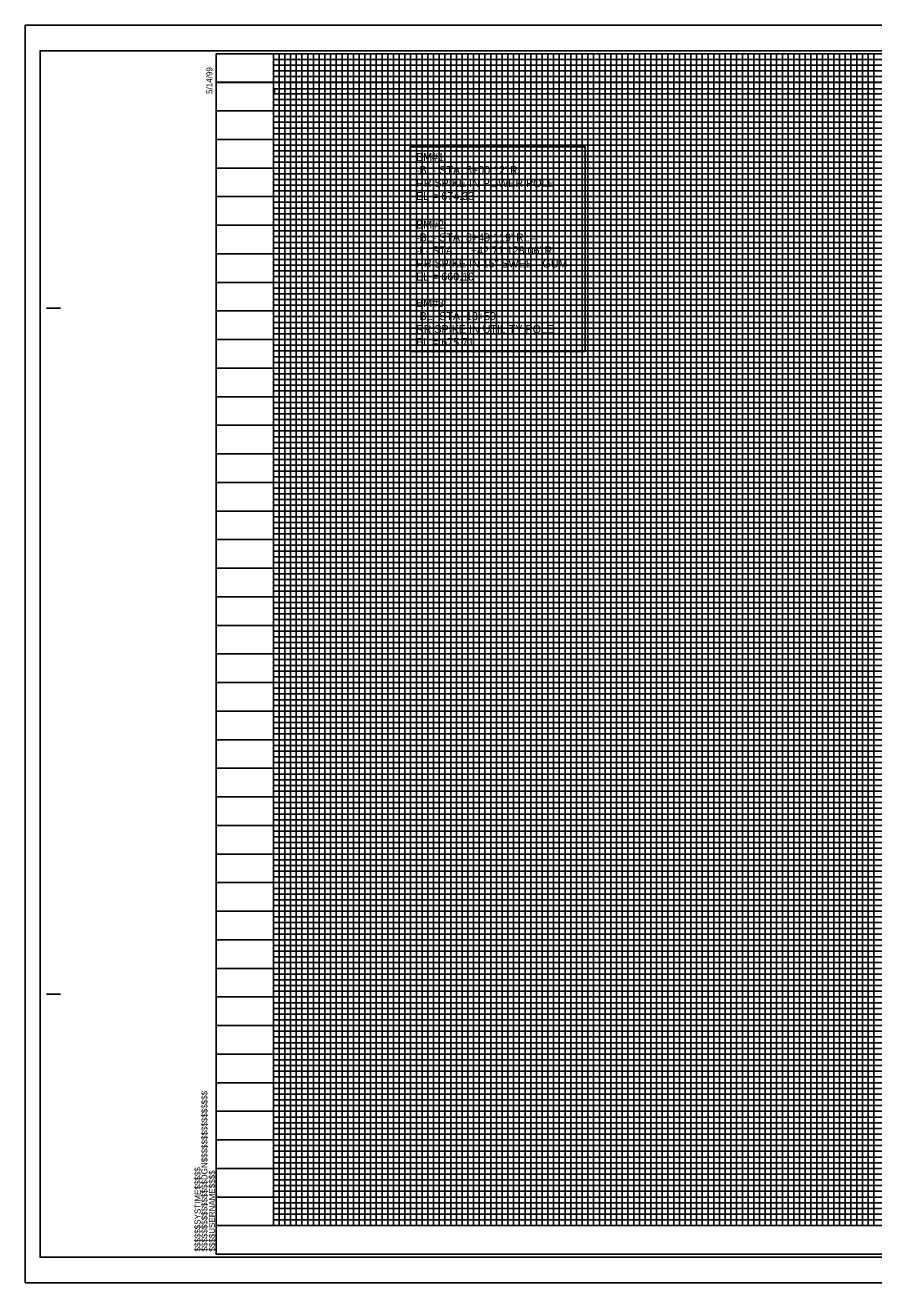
# Model space of a CAD drawing. Extents: x 566462 to 568359, y -52789 to -51689.
import ezdxf

# ---------------------------------------------------------------- set-up
doc = ezdxf.new("R2010")
doc.units = 0
for name, color, linetype in [('Prop Grid Mask', 7, 'Continuous'), ('Prop Roadway Profile Bench Mark Info Text', 7, 'Continuous'), ('Sheet Cutting Line CELL', 7, 'Continuous'), ('Sheet DOT Grid CELL', 7, 'Continuous'), ('Sheet Layout Profile Border', 7, 'Continuous'), ('Sheet Plot Border Inside CELL', 7, 'Continuous'), ('Sheet Plot Border Outside CELL', 7, 'Continuous'), ('Sheet Profile CELL', 7, 'Continuous'), ('Sheet Profile Grid Major CELL', 7, 'Continuous'), ('Sheet Profile Grid Middle CELL', 7, 'Continuous'), ('Sheet Profile Grid Minor CELL', 7, 'Continuous')]:
    doc.layers.add(name, color=color, linetype=linetype)

msp = doc.modelspace()

# ---------------------------------------------------------------- linework, layer by layer
at = {"layer": 'Prop Grid Mask'}
msp.add_lwpolyline([(566799.2, -51795.9), (566952, -51795.9), (566952, -51974.8), (566799.2, -51974.8)], close=True, dxfattribs=at)
at = {"layer": 'Sheet Cutting Line CELL'}
for p, q in [((568146.5, -51689.3), (566462.5, -51689.3)), ((566462.5, -51689.3), (566462.5, -52789.3)), ((566462.5, -52789.3), (568146.5, -52789.3))]:
    msp.add_line(p, q, dxfattribs=at)
at = {"layer": 'Sheet DOT Grid CELL'}
for p, q in [((566679.5, -51714.3), (566679.5, -52739.3)), ((566729.5, -51714.3), (566729.5, -52739.3)), ((566779.5, -51714.3), (566779.5, -52739.3)), ((566829.5, -51714.3), (566829.5, -52739.3)), ((566879.5, -51714.3), (566879.5, -52739.3)), ((566929.5, -51714.3), (566929.5, -52739.3)), ((566979.5, -51714.3), (566979.5, -52739.3)), ((567029.5, -51714.3), (567029.5, -52739.3)), ((567079.5, -51714.3), (567079.5, -52739.3)), ((567129.5, -51714.3), (567129.5, -52739.3)), ((567179.5, -51714.3), (567179.5, -52739.3)), ((566629.5, -51739.3), (567929.4, -51739.3)), ((566629.5, -51789.3), (567929.4, -51789.3)), ((566629.5, -51839.3), (567929.4, -51839.3)), ((566629.5, -51889.3), (568129.5, -51889.3)), ((566629.5, -51939.3), (568129.5, -51939.3)), ((566629.5, -51989.3), (568129.5, -51989.3)), ((566629.5, -52039.3), (568129.5, -52039.3)), ((566629.5, -52089.3), (568129.5, -52089.3)), ((566629.5, -52139.3), (568129.5, -52139.3)), ((566629.5, -52189.3), (568129.5, -52189.3)), ((566629.5, -52239.3), (568129.5, -52239.3)), ((566629.5, -52289.3), (568129.5, -52289.3)), ((566629.5, -52339.3), (568129.5, -52339.3)), ((566629.5, -52389.3), (568129.5, -52389.3)), ((566629.5, -52439.3), (568129.5, -52439.3)), ((566629.5, -52489.3), (568129.5, -52489.3)), ((566629.5, -52539.3), (568129.5, -52539.3)), ((566629.5, -52589.3), (568129.5, -52589.3)), ((566629.5, -52639.3), (568129.5, -52639.3)), ((566629.5, -52689.3), (568129.5, -52689.3))]:
    msp.add_line(p, q, dxfattribs=at)
at = {"layer": 'Sheet Layout Profile Border'}
msp.add_lwpolyline([(566679.5, -51714.3), (566679.5, -52739.3), (568079.5, -52739.3), (568079.5, -51851.9), (567929.4, -51851.9), (567929.4, -51714.3)], close=True, dxfattribs=at)
at = {"layer": 'Sheet Plot Border Inside CELL'}
msp.add_lwpolyline([(568142, -51711.8), (566475.5, -51711.8), (566475.5, -52766.9), (568142, -52766.9)], close=True, dxfattribs=at)
at = {"layer": 'Sheet Plot Border Outside CELL'}
msp.add_lwpolyline([(568146.5, -51689.3), (566462.5, -51689.3), (566462.5, -52789.3), (568146.5, -52789.3)], close=True, dxfattribs=at)
at = {"layer": 'Sheet Profile CELL'}
for p, q in [((566481, -51936.8), (566493.5, -51936.8)), ((566481, -52536.8), (566493.5, -52536.8)), ((568129.5, -52739.3), (566629.5, -52739.3)), ((566629.5, -52764.3), (566629.5, -52764.3)), ((566629.5, -52764.3), (566629.5, -52764.3)), ((566629.5, -52764.3), (566629.5, -52764.3)), ((566629.5, -52764.3), (566629.5, -52764.3)), ((566629.5, -52764.3), (566629.5, -52764.3)), ((566629.5, -52764.3), (566629.5, -52764.3))]:
    msp.add_line(p, q, dxfattribs=at)
msp.add_lwpolyline([(568129.5, -51714.3), (566629.5, -51714.3), (566629.5, -52764.3), (568129.5, -52764.3)], close=True, dxfattribs=at)
msp.add_lwpolyline([(566667, -52764.3), (566667, -52764.3)], dxfattribs=at)
at = {"layer": 'Sheet Profile Grid Major CELL'}
for points in [[(566629.5, -51714.3), (566679.5, -51714.3), (566679.5, -52739.3), (566729.5, -52739.3), (566729.5, -51714.3), (566779.5, -51714.3), (566779.5, -52739.3), (566829.5, -52739.3), (566829.5, -51714.3), (566879.5, -51714.3), (566879.5, -52739.3), (566929.5, -52739.3), (566929.5, -51714.3), (566979.5, -51714.3), (566979.5, -52739.3), (567029.5, -52739.3), (567029.5, -51714.3), (567079.5, -51714.3), (567079.5, -52739.3), (567129.5, -52739.3), (567129.5, -51714.3), (567179.5, -51714.3), (567179.5, -52739.3), (567229.5, -52739.3)], [(567929.4, -51789.3), (566629.6, -51789.3), (566629.6, -51739.4), (567929.4, -51739.4)], [(568129.5, -51889.3), (566629.5, -51889.3), (566629.5, -51839.3), (567929.4, -51839.3)], [(568129.5, -51989.3), (566629.5, -51989.3), (566629.5, -51939.3), (568129.5, -51939.3)], [(568129.5, -52089.3), (566629.5, -52089.3), (566629.5, -52039.3), (568129.5, -52039.3)], [(568129.5, -52189.3), (566629.5, -52189.3), (566629.5, -52139.3), (568129.5, -52139.3)], [(568129.5, -52289.3), (566629.5, -52289.3), (566629.5, -52239.3), (568129.5, -52239.3)], [(568129.5, -52389.3), (566629.5, -52389.3), (566629.5, -52339.3), (568129.5, -52339.3)], [(568129.5, -52489.3), (566629.5, -52489.3), (566629.5, -52439.3), (568129.5, -52439.3)], [(568129.5, -52589.3), (566629.5, -52589.3), (566629.5, -52539.3), (568129.5, -52539.3)], [(568129.5, -52689.3), (566629.5, -52689.3), (566629.5, -52639.3), (568129.5, -52639.3)]]:
    msp.add_lwpolyline(points, dxfattribs=at)
at = {"layer": 'Sheet Profile Grid Middle CELL'}
for points in [[(566704.5, -52739.3), (566704.5, -51714.3), (566754.5, -51714.3), (566754.5, -52739.3), (566804.5, -52739.3), (566804.5, -51714.3), (566854.5, -51714.3), (566854.5, -52739.3), (566904.5, -52739.3), (566904.5, -51714.3), (566954.5, -51714.3), (566954.5, -52739.3), (567004.5, -52739.3), (567004.5, -51714.3), (567054.5, -51714.3), (567054.5, -52739.3), (567104.5, -52739.3), (567104.5, -51714.3), (567154.5, -51714.3), (567154.5, -52739.3), (567204.5, -52739.3), (567204.5, -51714.3), (567254.5, -51714.3)], [(566629.5, -51764.3), (567929.4, -51764.3)], [(567929.4, -51814.3), (566629.5, -51814.3), (566629.5, -51864.4), (568129.5, -51864.4)], [(568129.5, -51914.3), (566629.5, -51914.3), (566629.5, -51964.3), (568129.5, -51964.3)], [(568129.5, -52014.3), (566629.5, -52014.3), (566629.5, -52064.3), (568129.5, -52064.3)], [(568129.5, -52114.3), (566629.5, -52114.3), (566629.5, -52164.3), (568129.5, -52164.3)], [(568129.5, -52214.3), (566629.5, -52214.3), (566629.5, -52264.3), (568129.5, -52264.3)], [(568129.5, -52314.3), (566629.5, -52314.3), (566629.5, -52364.3), (568129.5, -52364.3)], [(568129.5, -52414.3), (566629.5, -52414.3), (566629.5, -52464.3), (568129.5, -52464.3)], [(568129.5, -52514.3), (566629.5, -52514.3), (566629.5, -52564.3), (568129.5, -52564.3)], [(568129.5, -52614.3), (566629.5, -52614.3), (566629.5, -52664.3), (568129.5, -52664.3)], [(568129.5, -52714.3), (566629.5, -52714.3)]]:
    msp.add_lwpolyline(points, dxfattribs=at)
at = {"layer": 'Sheet Profile Grid Minor CELL'}
for p, q in [((568079.5, -51894.3), (566679.5, -51894.3)), ((566679.5, -51894.3), (566679.5, -51899.3)), ((566679.5, -51899.3), (568079.5, -51899.3)), ((568079.5, -51919.3), (566679.5, -51919.3))]:
    msp.add_line(p, q, dxfattribs=at)
for points in [[(566684.5, -51714.3), (566689.5, -51714.3), (566694.5, -51714.3), (566699.5, -51714.3), (566709.5, -51714.3), (566676.4, -51714.3), (566681.4, -51714.3), (566639.5, -51714.3), (566644.5, -51714.3), (566649.5, -51714.3), (566659.5, -51714.3), (566664.5, -51714.3), (566669.5, -51714.3), (566674.5, -51714.3), (566684.5, -51714.3), (566684.5, -52739.3), (566689.5, -52739.3), (566689.5, -51714.3), (566694.5, -51714.3), (566694.5, -52739.3), (566699.5, -52739.3), (566699.5, -51714.3), (566709.5, -51714.3), (566709.5, -52739.3), (566714.5, -52739.3), (566714.5, -51714.3), (566719.5, -51714.3), (566719.5, -52739.3), (566724.5, -52739.3), (566724.5, -51714.3), (566734.5, -51714.3), (566734.5, -52739.3), (566739.5, -52739.3), (566739.5, -51714.3), (566744.5, -51714.3), (566744.5, -52739.3), (566749.5, -52739.3), (566749.5, -51714.3), (566759.5, -51714.3), (566759.5, -52739.3), (566764.5, -52739.3), (566764.5, -51714.3), (566769.5, -51714.3), (566769.5, -52739.3), (566774.5, -52739.3), (566774.5, -51714.3), (566784.5, -51714.3), (566784.5, -52739.3), (566789.5, -52739.3), (566789.5, -51714.3), (566794.5, -51714.3), (566794.5, -52739.3), (566799.5, -52739.3), (566799.5, -51714.3), (566809.5, -51714.3), (566809.5, -52739.3), (566814.5, -52739.3), (566814.5, -51714.3), (566819.5, -51714.3), (566819.5, -52739.3), (566824.5, -52739.3), (566824.5, -51714.3), (566834.5, -51714.3), (566834.5, -52739.3), (566839.5, -52739.3), (566839.5, -51714.3), (566844.5, -51714.3), (566844.5, -52739.3)], [(567929.4, -51719.3), (566679.5, -51719.3), (566679.5, -51724.3), (567929.4, -51724.3)], [(566844.5, -52739.3), (566849.5, -52739.3), (566849.5, -51714.3), (566859.5, -51714.3), (566859.5, -52739.3), (566864.5, -52739.3), (566864.5, -51714.3), (566869.5, -51714.3), (566869.5, -52739.3), (566874.5, -52739.3), (566874.5, -51714.3), (566884.5, -51714.3), (566884.5, -52739.3), (566889.5, -52739.3), (566889.5, -51714.3), (566889.5, -51714.3), (566894.5, -51714.3), (566894.5, -52739.3), (566899.5, -52739.3), (566899.5, -51714.3), (566909.5, -51714.3), (566909.5, -52739.3), (566914.5, -52739.3), (566914.5, -51714.3), (566919.5, -51714.3), (566919.5, -52739.3), (566924.5, -52739.3), (566924.5, -51714.3), (566934.5, -51714.3), (566934.5, -52739.3), (566939.5, -52739.3), (566939.5, -51714.3), (566944.5, -51714.3), (566944.5, -52739.3), (566949.5, -52739.3), (566949.5, -51714.3), (566959.5, -51714.3), (566959.5, -52739.3), (566964.5, -52739.3), (566964.5, -51714.3), (566969.5, -51714.3), (566969.5, -52739.3), (566974.5, -52739.3), (566974.5, -51714.3), (566984.5, -51714.3), (566984.5, -52739.3), (566989.5, -52739.3), (566989.5, -51714.3), (566994.5, -51714.3), (566994.5, -52739.3), (566999.5, -52739.3), (566999.5, -51714.3), (567009.5, -51714.3), (567009.5, -52739.3), (567024.5, -52739.3), (567024.5, -51714.3), (567034.5, -51714.3), (567034.5, -52739.3), (567039.5, -52739.3), (567039.5, -51714.3), (567044.5, -51714.3), (567044.5, -52739.3), (567049.5, -52739.3), (567049.5, -51714.3), (567059.5, -51714.3), (567059.5, -52739.3), (567064.5, -52739.3), (567064.5, -51714.3), (567069.5, -51714.3), (567069.5, -52739.3), (567074.5, -52739.3), (567074.5, -51714.3), (567084.5, -51714.3), (567084.5, -52739.3), (567089.5, -52739.3), (567089.5, -51714.3), (567094.5, -51714.3), (567094.5, -52739.3), (567099.5, -52739.3), (567099.5, -51714.3), (567109.5, -51714.3), (567109.5, -52739.3), (567114.5, -52739.3), (567114.5, -51714.3), (567119.5, -51714.3), (567119.5, -52739.3), (567124.5, -52739.3), (567124.5, -51714.3), (567134.5, -51714.3), (567134.5, -52739.3), (567139.5, -52739.3), (567139.5, -51714.3), (567144.5, -51714.3), (567144.5, -52739.3), (567149.5, -52739.3), (567149.5, -51714.3), (567159.5, -51714.3), (567159.5, -52739.3)], [(567014.5, -51714.3), (567014.5, -52739.3), (567019.5, -52739.3), (567019.5, -51714.3)], [(567014.5, -51714.9), (567014.5, -52739.3), (567019.5, -52739.3), (567019.5, -51714.9)], [(567164.5, -51714.3), (567164.5, -52739.3), (567169.5, -52739.3), (567169.5, -51714.3), (567174.5, -51714.3), (567174.5, -52739.3), (567184.5, -52739.3), (567184.5, -51714.3), (567189.5, -51714.3), (567189.5, -52739.3), (567194.5, -52739.3), (567194.5, -51714.3), (567199.5, -51714.3), (567199.5, -52739.3)], [(567929.4, -51729.3), (566679.5, -51729.3), (566679.5, -51734.3), (567929.4, -51734.3)], [(567929.4, -51754.3), (566679.5, -51754.3), (566679.5, -51759.3), (567929.4, -51759.3)], [(567929.4, -51745.1), (566680.5, -51745.1), (566680.5, -51749.3), (567929.4, -51749.3)], [(567929.4, -51769.3), (566679.5, -51769.3), (566679.5, -51774.3), (567929.4, -51774.3)], [(567929.4, -51779.3), (566679.5, -51779.3), (566679.5, -51784.3), (567929.4, -51784.3)], [(567929.4, -51794.3), (566679.5, -51794.3), (566679.5, -51799.3), (567929.4, -51799.3)], [(567929.4, -51804.3), (566679.5, -51804.3), (566679.5, -51809.3), (567929.4, -51809.3)], [(567929.4, -51819.3), (566679.5, -51819.3), (566679.5, -51824.3), (567929.4, -51824.3)], [(567929.4, -51829.3), (566679.5, -51829.3), (566679.5, -51834.3), (567929.4, -51834.3)], [(567929.4, -51844.3), (566679.5, -51844.3), (566679.5, -51849.3), (567929.4, -51849.3)], [(568079.5, -51854.3), (566679.5, -51854.3), (566679.5, -51854.3), (566679.5, -51874.3), (568079.5, -51874.3)], [(566679.5, -51859.3), (568079.5, -51859.3)], [(568079.5, -51869.3), (566679.5, -51869.3)], [(568079.5, -51879.3), (566679.5, -51879.3), (566679.5, -51884.3), (568079.5, -51884.3)], [(568079.5, -51904.3), (566679.5, -51904.3), (566679.5, -51909.3), (568079.5, -51909.3)], [(568079.5, -51924.3), (566679.5, -51924.3), (566679.5, -51929.3), (568079.5, -51929.3)], [(568079.5, -51934.3), (566679.5, -51934.3)], [(566679.5, -51944.3), (568079.5, -51944.3)], [(568079.5, -51949.3), (566679.5, -51949.3), (566679.5, -51954.3), (568079.5, -51954.3)], [(568079.5, -51959.3), (566679.5, -51959.3), (566679.5, -51969.3), (568079.5, -51969.3)], [(568079.5, -51974.3), (566679.5, -51974.3), (566679.5, -51979.3), (568079.5, -51979.3)], [(568079.5, -51984.3), (566679.5, -51984.3), (566679.5, -51994.3), (568079.5, -51994.3)], [(568079.5, -51999.3), (566679.5, -51999.3), (566679.5, -52004.3), (568079.5, -52004.3)], [(568079.5, -52009.3), (566679.5, -52009.3), (566679.5, -52019.3), (568079.5, -52019.3)], [(568079.5, -52024.3), (566679.5, -52024.3), (566679.5, -52029.3), (568079.5, -52029.3)], [(568079.5, -52034.3), (566679.5, -52034.3), (566679.5, -52044.3), (568079.5, -52044.3)], [(568079.5, -52049.3), (566679.5, -52049.3), (566679.5, -52054.3), (568079.5, -52054.3)], [(568079.5, -52059.3), (566679.5, -52059.3), (566679.5, -52069.3), (568079.5, -52069.3)], [(568079.5, -52074.3), (566679.5, -52074.3), (566679.5, -52079.3), (568079.5, -52079.3)], [(568079.5, -52084.3), (566679.5, -52084.3), (566679.5, -52094.3), (568079.5, -52094.3)], [(568079.5, -52099.3), (566679.5, -52099.3), (566679.5, -52104.3), (568079.5, -52104.3)], [(568079.5, -52109.3), (566679.5, -52109.3), (566679.5, -52119.3), (568079.5, -52119.3)], [(568079.5, -52124.3), (566679.5, -52124.3), (566679.5, -52129.3), (568079.5, -52129.3)], [(568079.5, -52134.3), (566679.5, -52134.3), (566679.5, -52144.3), (568079.5, -52144.3)], [(568079.5, -52149.3), (566679.5, -52149.3), (566679.5, -52154.3), (568079.5, -52154.3)], [(568079.5, -52159.3), (566679.5, -52159.3), (566679.5, -52169.3), (568079.5, -52169.3)], [(568079.5, -52174.3), (566679.5, -52174.3), (566679.5, -52179.3), (568079.5, -52179.3)], [(568079.5, -52184.3), (566679.5, -52184.3), (566679.5, -52194.3), (568079.5, -52194.3)], [(568079.5, -52199.3), (566679.5, -52199.3), (566679.5, -52204.3), (568079.5, -52204.3)], [(568079.5, -52209.3), (566679.5, -52209.3), (566679.5, -52219.3), (568079.5, -52219.3)], [(568079.5, -52224.3), (566679.5, -52224.3), (566679.5, -52229.3), (568079.5, -52229.3)], [(568079.5, -52234.3), (566679.5, -52234.3)], [(566679.5, -52244.3), (568079.5, -52244.3)], [(568079.5, -52249.3), (566679.5, -52249.3), (566679.5, -52254.3), (568079.5, -52254.3)], [(568079.5, -52259.3), (566679.5, -52259.3), (566679.5, -52269.3), (568079.5, -52269.3)], [(568079.5, -52274.3), (566679.5, -52274.3), (566679.5, -52279.3), (568079.5, -52279.3)], [(568079.5, -52284.3), (566679.5, -52284.3), (566679.5, -52294.3), (568079.5, -52294.3)], [(568079.5, -52299.3), (566679.5, -52299.3), (566679.5, -52304.3), (568079.5, -52304.3)], [(568079.5, -52309.3), (566679.5, -52309.3), (566679.5, -52319.3), (568079.5, -52319.3)], [(568079.5, -52324.3), (566679.5, -52324.3), (566679.5, -52329.3), (568079.5, -52329.3)], [(568079.5, -52334.3), (566679.5, -52334.3), (566679.5, -52344.3), (568079.5, -52344.3)], [(568079.5, -52349.3), (566679.5, -52349.3), (566679.5, -52354.3), (568079.5, -52354.3)], [(568079.5, -52359.3), (566679.5, -52359.3), (566679.5, -52369.3), (568079.5, -52369.3)], [(568079.5, -52374.3), (566679.5, -52374.3), (566679.5, -52379.3), (568079.5, -52379.3)], [(568079.5, -52384.3), (566679.5, -52384.3), (566679.5, -52394.3), (568079.5, -52394.3)], [(568079.5, -52399.3), (566679.5, -52399.3), (566679.5, -52404.3), (568079.5, -52404.3)], [(568079.5, -52409.3), (566679.5, -52409.3), (566679.5, -52419.3), (568079.5, -52419.3)], [(568079.5, -52424.3), (566679.5, -52424.3), (566679.5, -52429.3), (568079.5, -52429.3)], [(568079.5, -52434.3), (566679.5, -52434.3), (566679.5, -52444.3), (568079.5, -52444.3)], [(568079.5, -52449.3), (566679.5, -52449.3), (566679.5, -52454.3), (568079.5, -52454.3)], [(568079.5, -52459.3), (566679.5, -52459.3), (566679.5, -52469.3), (568079.5, -52469.3)], [(568079.5, -52474.3), (566679.5, -52474.3), (566679.5, -52479.3), (568079.5, -52479.3)], [(568079.5, -52484.3), (566679.5, -52484.3), (566679.5, -52494.3), (568079.5, -52494.3)], [(568079.5, -52499.3), (566679.5, -52499.3), (566679.5, -52504.3), (568079.5, -52504.3)], [(568079.5, -52509.3), (566679.5, -52509.3), (566679.5, -52519.3), (568079.5, -52519.3)], [(568079.5, -52524.3), (566679.5, -52524.3), (566679.5, -52529.3), (568079.5, -52529.3)], [(568079.5, -52534.3), (566679.5, -52534.3)], [(566679.5, -52544.3), (568079.5, -52544.3)], [(568079.5, -52549.3), (566679.5, -52549.3), (566679.5, -52554.3), (568079.5, -52554.3)], [(568079.5, -52559.3), (566679.5, -52559.3)], [(566679.5, -52569.3), (568079.5, -52569.3)], [(568079.5, -52574.3), (566679.5, -52574.3), (566679.5, -52579.3), (568079.5, -52579.3)], [(568079.5, -52584.3), (566679.5, -52584.3), (566679.5, -52594.3), (568079.5, -52594.3)], [(568079.5, -52599.3), (566679.5, -52599.3), (566679.5, -52604.3), (568079.5, -52604.3)], [(568079.5, -52609.3), (566679.5, -52609.3), (566679.5, -52619.3), (568079.5, -52619.3)], [(568079.5, -52624.3), (566679.5, -52624.3), (566679.5, -52629.3), (568079.5, -52629.3)], [(568079.5, -52634.3), (566679.5, -52634.3), (566679.5, -52644.3), (568079.5, -52644.3)], [(568079.5, -52649.3), (566679.5, -52649.3), (566679.5, -52654.3), (568079.5, -52654.3)], [(568079.5, -52659.3), (566679.5, -52659.3), (566679.5, -52669.3), (568079.5, -52669.3)], [(568079.5, -52674.3), (566679.5, -52674.3), (566679.5, -52679.3), (568079.5, -52679.3)], [(568079.5, -52684.3), (566679.5, -52684.3), (566679.5, -52694.3), (568079.5, -52694.3)], [(568079.5, -52699.3), (566679.5, -52699.3), (566679.5, -52704.3), (568079.5, -52704.3)], [(568079.5, -52709.3), (566679.5, -52709.3), (566679.5, -52719.3), (568079.5, -52719.3)], [(568079.5, -52724.3), (566679.5, -52724.3), (566679.5, -52729.3), (568079.5, -52729.3)], [(568079.5, -52734.3), (566679.5, -52734.3)]]:
    msp.add_lwpolyline(points, dxfattribs=at)

# ---------------------------------------------------------------- texts
at = {"layer": 'Prop Roadway Profile Bench Mark Info Text'}
for s, p in [('BM#1', (566804.2, -51808.2)), ("-BL- STA. 5+00 12' Rt.", (566804.2, -51819.6)), ('RR SPIKE IN POWER POLE', (566804.2, -51831)), ('EL = 674.33', (566804.2, -51842.3)), ('BM#2', (566804.2, -51867.2)), ("-BL- STA. 8+49 119' Rt.=", (566804.2, -51878.5)), ("-L- STA. 11+42.71 128.06' Rt.", (566804.2, -51889.9)), ('RR SPIKE IN 15" SWEET GUM', (566804.2, -51901.3)), ('EL = 660.10', (566804.2, -51912.7)), ('BM#3', (566804.2, -51935.9)), ('-BL- STA. 13+59', (566804.2, -51947.3)), ('RR SPIKE IN UTILITY POLE', (566804.2, -51958.7)), ('EL = 675.71', (566804.2, -51970.1))]:
    msp.add_text(s, height=7, dxfattribs=at).set_placement(p)
at = {"layer": 'Sheet Profile CELL'}
for s, p in [('5/14/99', (566626.2, -51749.5)), ('$$$$$$$$$$$$$$$$DGN$$$$$$$$$$$$$$$$', (566621.8, -52762)), ('$$$$$$SYSTIME$$$$$', (566615.8, -52762)), ('$$$$USERNAME$$$$', (566628.4, -52762))]:
    msp.add_text(s, height=5.25, rotation=90, dxfattribs=at).set_placement(p)

doc.saveas('drawing.dxf')
